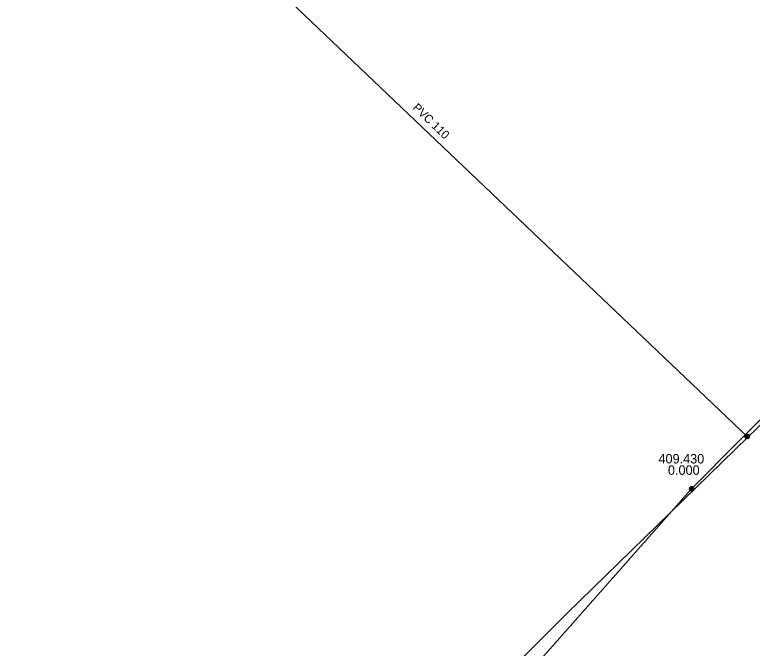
# Model space of a CAD drawing. Extents: x -867104 to -866746, y -1014489 to -1014255.
# Drawn here: x -866892.5 to -866822.4, y -1014399.4 to -1014339.3 of the extents above; entities that cross this region are included whole.
import ezdxf

# ---------------------------------------------------------------- set-up
doc = ezdxf.new("R2010")
doc.units = 0
doc.header["$LTSCALE"] = 0.44
for name, color, linetype, lineweight in [('1', 7, 'Continuous', 35), ('12', 7, 'Continuous', 13), ('21', 7, 'Continuous', 35), ('3', 7, 'Continuous', 25), ('32', 7, 'Continuous', 13)]:
    doc.layers.add(name, color=color, linetype=linetype, lineweight=lineweight)

msp = doc.modelspace()

# ---------------------------------------------------------------- linework, layer by layer
at = {"layer": '1'}
for points in [[(-866762.254, -1014321.165), (-866822.841, -1014379.375), (-866840.01, -1014396.11)], [(-866840.01, -1014396.11), (-866844.69, -1014400.78), (-866847.06, -1014402.96), (-866848.88, -1014406.15), (-866860.28, -1014424.67), (-866871.77, -1014440.29), (-866875.11, -1014444.27), (-866876.93, -1014446.09), (-866879, -1014449.37), (-866879.17, -1014450.73), (-866879.17, -1014451.68), (-866879.03, -1014452.53), (-866876.52, -1014455.41), (-866874.72, -1014458.69), (-866874.8, -1014459.33), (-866875.66, -1014460.47), (-866876.85, -1014461.77), (-866877.992, -1014463.135), (-866881.12, -1014466.73), (-866885.53, -1014471.37), (-866892.467, -1014476.423)]]:
    msp.add_lwpolyline(points, dxfattribs=at)
at = {"layer": '12'}
for points in [[(-866822.668, -1014379.32), (-866822.674, -1014379.268), (-866822.691, -1014379.218), (-866822.72, -1014379.174), (-866822.757, -1014379.137), (-866822.802, -1014379.11), (-866822.852, -1014379.093), (-866822.905, -1014379.089), (-866822.956, -1014379.096), (-866823.005, -1014379.115), (-866823.049, -1014379.144), (-866823.085, -1014379.183), (-866823.111, -1014379.228), (-866823.127, -1014379.279), (-866823.13, -1014379.331), (-866823.122, -1014379.383), (-866823.102, -1014379.432), (-866823.071, -1014379.475), (-866823.032, -1014379.509), (-866822.986, -1014379.535), (-866822.934, -1014379.549), (-866822.882, -1014379.551), (-866822.831, -1014379.541), (-866822.782, -1014379.52), (-866822.74, -1014379.489), (-866822.706, -1014379.448), (-866822.682, -1014379.402), (-866822.669, -1014379.351)], [(-866822.698, -1014379.32), (-866822.704, -1014379.271), (-866822.721, -1014379.225), (-866822.749, -1014379.185), (-866822.786, -1014379.153), (-866822.83, -1014379.131), (-866822.878, -1014379.12), (-866822.927, -1014379.12), (-866822.973, -1014379.133), (-866823.017, -1014379.157), (-866823.053, -1014379.19), (-866823.08, -1014379.231), (-866823.096, -1014379.278), (-866823.1, -1014379.327), (-866823.093, -1014379.375), (-866823.074, -1014379.42), (-866823.044, -1014379.46), (-866823.005, -1014379.491), (-866822.962, -1014379.511), (-866822.914, -1014379.521), (-866822.865, -1014379.519), (-866822.818, -1014379.504), (-866822.775, -1014379.479), (-866822.74, -1014379.445), (-866822.715, -1014379.403), (-866822.701, -1014379.356)], [(-866822.728, -1014379.32), (-866822.733, -1014379.275), (-866822.75, -1014379.233), (-866822.779, -1014379.198), (-866822.815, -1014379.171), (-866822.857, -1014379.154), (-866822.902, -1014379.149), (-866822.946, -1014379.155), (-866822.988, -1014379.174), (-866823.022, -1014379.202), (-866823.049, -1014379.239), (-866823.066, -1014379.281), (-866823.07, -1014379.326), (-866823.063, -1014379.371), (-866823.044, -1014379.412), (-866823.015, -1014379.446), (-866822.978, -1014379.472), (-866822.934, -1014379.488), (-866822.89, -1014379.491), (-866822.845, -1014379.483), (-866822.804, -1014379.463), (-866822.771, -1014379.434), (-866822.745, -1014379.396), (-866822.731, -1014379.353)], [(-866822.758, -1014379.32), (-866822.762, -1014379.279), (-866822.781, -1014379.242), (-866822.808, -1014379.211), (-866822.843, -1014379.19), (-866822.883, -1014379.179), (-866822.924, -1014379.181), (-866822.963, -1014379.194), (-866822.997, -1014379.218), (-866823.022, -1014379.25), (-866823.037, -1014379.288), (-866823.039, -1014379.329), (-866823.032, -1014379.369), (-866823.012, -1014379.405), (-866822.983, -1014379.434), (-866822.946, -1014379.453), (-866822.906, -1014379.461), (-866822.865, -1014379.457), (-866822.826, -1014379.442), (-866822.794, -1014379.416), (-866822.772, -1014379.382), (-866822.759, -1014379.343)], [(-866822.788, -1014379.32), (-866822.793, -1014379.284), (-866822.811, -1014379.252), (-866822.837, -1014379.227), (-866822.87, -1014379.212), (-866822.907, -1014379.209), (-866822.941, -1014379.217), (-866822.973, -1014379.237), (-866822.995, -1014379.265), (-866823.009, -1014379.299), (-866823.009, -1014379.336), (-866822.998, -1014379.371), (-866822.977, -1014379.4), (-866822.946, -1014379.421), (-866822.912, -1014379.431), (-866822.875, -1014379.429), (-866822.841, -1014379.415), (-866822.814, -1014379.392), (-866822.794, -1014379.36), (-866822.788, -1014379.325)], [(-866822.818, -1014379.32), (-866822.823, -1014379.289), (-866822.84, -1014379.263), (-866822.865, -1014379.246), (-866822.896, -1014379.239), (-866822.927, -1014379.243), (-866822.954, -1014379.26), (-866822.972, -1014379.284), (-866822.98, -1014379.315), (-866822.976, -1014379.345), (-866822.961, -1014379.373), (-866822.936, -1014379.392), (-866822.907, -1014379.401), (-866822.875, -1014379.398), (-866822.848, -1014379.384), (-866822.828, -1014379.36), (-866822.818, -1014379.331)], [(-866822.848, -1014379.32), (-866822.853, -1014379.296), (-866822.87, -1014379.278), (-866822.892, -1014379.269), (-866822.917, -1014379.272), (-866822.938, -1014379.286), (-866822.949, -1014379.308), (-866822.949, -1014379.333), (-866822.936, -1014379.354), (-866822.917, -1014379.368), (-866822.892, -1014379.371), (-866822.869, -1014379.362), (-866822.853, -1014379.344)], [(-866822.878, -1014379.32), (-866822.883, -1014379.305), (-866822.897, -1014379.299), (-866822.913, -1014379.303), (-866822.919, -1014379.317), (-866822.916, -1014379.332), (-866822.902, -1014379.341), (-866822.887, -1014379.338), (-866822.878, -1014379.326)]]:
    msp.add_lwpolyline(points, close=True, dxfattribs=at)
at = {"layer": '21'}
msp.add_lwpolyline([(-866846.197, -1014404.673), (-866828.183, -1014384.303), (-866770.762, -1014326.42)], dxfattribs=at)
at = {"layer": '3'}
msp.add_lwpolyline([(-866822.842, -1014379.376), (-866822.91, -1014379.31), (-866883.327, -1014321.768)], dxfattribs=at)
at = {"layer": '32'}
for points in [[(-866827.951, -1014384.303), (-866827.958, -1014384.251), (-866827.975, -1014384.201), (-866828.004, -1014384.157), (-866828.041, -1014384.12), (-866828.086, -1014384.093), (-866828.136, -1014384.076), (-866828.189, -1014384.072), (-866828.24, -1014384.079), (-866828.289, -1014384.098), (-866828.333, -1014384.127), (-866828.369, -1014384.166), (-866828.395, -1014384.211), (-866828.411, -1014384.262), (-866828.414, -1014384.314), (-866828.406, -1014384.366), (-866828.386, -1014384.415), (-866828.355, -1014384.458), (-866828.316, -1014384.492), (-866828.27, -1014384.518), (-866828.218, -1014384.532), (-866828.166, -1014384.534), (-866828.115, -1014384.524), (-866828.066, -1014384.503), (-866828.024, -1014384.472), (-866827.99, -1014384.431), (-866827.966, -1014384.385), (-866827.953, -1014384.334)], [(-866827.982, -1014384.303), (-866827.988, -1014384.254), (-866828.005, -1014384.208), (-866828.032, -1014384.168), (-866828.07, -1014384.136), (-866828.114, -1014384.114), (-866828.162, -1014384.103), (-866828.211, -1014384.103), (-866828.257, -1014384.116), (-866828.301, -1014384.14), (-866828.337, -1014384.173), (-866828.364, -1014384.214), (-866828.38, -1014384.261), (-866828.384, -1014384.31), (-866828.377, -1014384.358), (-866828.358, -1014384.403), (-866828.328, -1014384.443), (-866828.289, -1014384.474), (-866828.245, -1014384.494), (-866828.198, -1014384.504), (-866828.149, -1014384.502), (-866828.102, -1014384.487), (-866828.059, -1014384.462), (-866828.024, -1014384.428), (-866827.999, -1014384.386), (-866827.985, -1014384.339)], [(-866828.012, -1014384.303), (-866828.017, -1014384.258), (-866828.034, -1014384.216), (-866828.063, -1014384.181), (-866828.098, -1014384.154), (-866828.141, -1014384.137), (-866828.186, -1014384.132), (-866828.23, -1014384.138), (-866828.272, -1014384.157), (-866828.306, -1014384.185), (-866828.333, -1014384.222), (-866828.35, -1014384.264), (-866828.353, -1014384.309), (-866828.347, -1014384.354), (-866828.328, -1014384.395), (-866828.299, -1014384.429), (-866828.262, -1014384.455), (-866828.218, -1014384.471), (-866828.174, -1014384.474), (-866828.129, -1014384.466), (-866828.088, -1014384.446), (-866828.054, -1014384.417), (-866828.029, -1014384.379), (-866828.015, -1014384.336)], [(-866828.042, -1014384.303), (-866828.046, -1014384.262), (-866828.065, -1014384.225), (-866828.092, -1014384.194), (-866828.127, -1014384.173), (-866828.167, -1014384.162), (-866828.208, -1014384.164), (-866828.247, -1014384.177), (-866828.281, -1014384.201), (-866828.306, -1014384.233), (-866828.321, -1014384.271), (-866828.323, -1014384.312), (-866828.316, -1014384.352), (-866828.296, -1014384.388), (-866828.267, -1014384.417), (-866828.23, -1014384.436), (-866828.19, -1014384.444), (-866828.149, -1014384.44), (-866828.11, -1014384.425), (-866828.078, -1014384.399), (-866828.056, -1014384.365), (-866828.043, -1014384.326)], [(-866828.071, -1014384.303), (-866828.076, -1014384.267), (-866828.095, -1014384.235), (-866828.12, -1014384.21), (-866828.154, -1014384.195), (-866828.191, -1014384.192), (-866828.225, -1014384.2), (-866828.257, -1014384.22), (-866828.279, -1014384.248), (-866828.293, -1014384.282), (-866828.293, -1014384.319), (-866828.282, -1014384.354), (-866828.261, -1014384.383), (-866828.23, -1014384.404), (-866828.196, -1014384.414), (-866828.159, -1014384.412), (-866828.125, -1014384.398), (-866828.098, -1014384.375), (-866828.078, -1014384.343), (-866828.071, -1014384.308)], [(-866828.102, -1014384.303), (-866828.107, -1014384.272), (-866828.124, -1014384.246), (-866828.149, -1014384.229), (-866828.179, -1014384.222), (-866828.211, -1014384.226), (-866828.238, -1014384.243), (-866828.255, -1014384.267), (-866828.264, -1014384.298), (-866828.26, -1014384.328), (-866828.245, -1014384.356), (-866828.22, -1014384.375), (-866828.191, -1014384.384), (-866828.159, -1014384.381), (-866828.132, -1014384.367), (-866828.112, -1014384.343), (-866828.102, -1014384.314)], [(-866828.132, -1014384.303), (-866828.137, -1014384.279), (-866828.154, -1014384.261), (-866828.176, -1014384.252), (-866828.201, -1014384.255), (-866828.222, -1014384.269), (-866828.233, -1014384.291), (-866828.233, -1014384.316), (-866828.22, -1014384.337), (-866828.201, -1014384.351), (-866828.176, -1014384.354), (-866828.152, -1014384.345), (-866828.137, -1014384.327)], [(-866828.162, -1014384.303), (-866828.167, -1014384.288), (-866828.181, -1014384.282), (-866828.196, -1014384.286), (-866828.203, -1014384.3), (-866828.2, -1014384.315), (-866828.186, -1014384.324), (-866828.171, -1014384.321), (-866828.162, -1014384.309)]]:
    msp.add_lwpolyline(points, close=True, dxfattribs=at)

# ---------------------------------------------------------------- texts
at = {"layer": '1'}
msp.add_text('PVC 110 ', height=0.8, rotation=316, dxfattribs=at).set_placement((-866854.732, -1014348.173))
for s, p in [('409.430 ', (-866831.332, -1014381.887)), ('0.000 ', (-866830.432, -1014382.964))]:
    msp.add_text(s, height=0.9, dxfattribs=at).set_placement(p)

doc.saveas('drawing.dxf')
